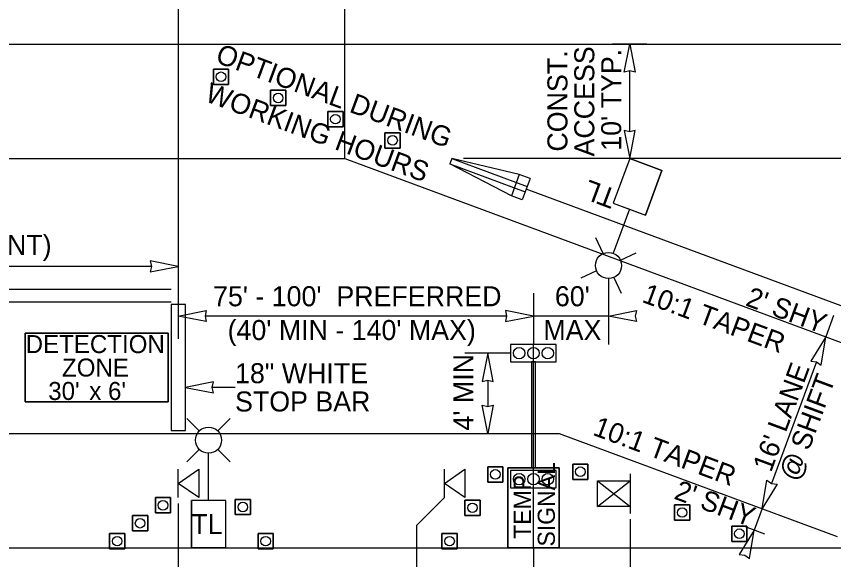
# Model space of a CAD drawing. Extents: x 99977 to 100176, y 99905 to 100011.
# Drawn here: x 100009.291 to 100012.15, y 100006.138 to 100008.036 of the extents above; entities that cross this region are included whole.
import ezdxf

# ---------------------------------------------------------------- set-up
doc = ezdxf.new("R2010")
doc.units = 0
for name, color, linetype in [('RD_ED_ShoulderPavedEdge', 7, 'Continuous'), ('RD_MK_LineEdgeWhite', 7, 'Continuous'), ('RD_MK_LineNoPass', 7, 'Continuous'), ('TR_WZ_BarrierTemp', 7, 'Continuous'), ('TR_WZ_PortableLightStandard', 7, 'Continuous'), ('TR_WZ_PortableSignMount5ftMinBlk-Wht', 7, 'Continuous'), ('TR_WZ_PortableSignMountBlk-Wht', 7, 'Continuous'), ('TR_WZ_ScaleTerminalEndSection', 7, 'Continuous'), ('TR_WZ_TempSignal', 7, 'Continuous'), ('TR_WZ_TrafficCone', 7, 'Continuous'), ('TR_WZ_WorkZoneDetails', 7, 'Continuous'), ('TR_WZ_WorkZoneTextCurrent', 7, 'Continuous')]:
    doc.layers.add(name, color=color, linetype=linetype)

msp = doc.modelspace()

# ---------------------------------------------------------------- linework, layer by layer
at = {"layer": 'RD_ED_ShoulderPavedEdge'}
for p, q in [((100000.1076, 100007.9393), (100015.45, 100007.9393)), ((100000.1076, 100006.1793), (100015.45, 100006.1793))]:
    msp.add_line(p, q, dxfattribs=at)
at = {"layer": 'RD_MK_LineEdgeWhite'}
for p, q in [((100000.1076, 100007.5393), (100010.4406, 100007.5393)), ((100010.4406, 100007.5393), (100012.9246, 100006.6193)), ((100000.1076, 100006.5793), (100011.1899, 100006.5793)), ((100011.1899, 100006.5793), (100012.1619, 100006.2193))]:
    msp.add_line(p, q, dxfattribs=at)
at = {"layer": 'RD_MK_LineNoPass'}
for p, q in [((100006.4076, 100007.0826), (100009.8326, 100007.0826)), ((100006.4076, 100007.0393), (100009.8326, 100007.0393))]:
    msp.add_line(p, q, dxfattribs=at)
at = {"layer": 'TR_WZ_BarrierTemp'}
msp.add_line((100012.9895, 100006.7232), (100011.074, 100007.4327), dxfattribs=at)
at = {"layer": 'TR_WZ_PortableLightStandard'}
for p, q in [((100011.4367, 100007.5393), (100011.3791, 100007.3837)), ((100011.4367, 100007.5393), (100011.3791, 100007.3837)), ((100011.4367, 100007.5393), (100011.5492, 100007.4976)), ((100011.5492, 100007.4976), (100011.4916, 100007.342)), ((100011.4916, 100007.342), (100011.5492, 100007.4976)), ((100011.4353, 100007.3628), (100011.3782, 100007.2087)), ((100011.3791, 100007.3837), (100011.4916, 100007.342)), ((100011.3432, 100007.2073), (100011.3178, 100007.2626)), ((100011.4039, 100007.1848), (100011.4593, 100007.2103)), ((100011.3207, 100007.1467), (100011.2655, 100007.1212)), ((100011.3815, 100007.1242), (100011.4069, 100007.0688)), ((100009.9312, 100006.5878), (100009.8881, 100006.6309)), ((100009.996, 100006.5878), (100010.0389, 100006.6309)), ((100009.9312, 100006.5231), (100009.8881, 100006.48)), ((100009.9636, 100006.3453), (100009.9636, 100006.5097)), ((100009.996, 100006.5231), (100010.0389, 100006.48)), ((100009.9036, 100006.1793), (100009.9036, 100006.3453)), ((100010.0236, 100006.3453), (100009.9036, 100006.3453)), ((100009.9036, 100006.3453), (100009.9036, 100006.1793)), ((100010.0236, 100006.1793), (100010.0236, 100006.3453)), ((100010.0236, 100006.1793), (100010.0236, 100006.3453)), ((100010.0236, 100006.1793), (100009.9036, 100006.1793))]:
    msp.add_line(p, q, dxfattribs=at)
for points in [[(100011.5492, 100007.4976), (100011.493, 100007.5185), (100011.4367, 100007.5393)], [(100011.3791, 100007.3837), (100011.4353, 100007.3628), (100011.4916, 100007.342)], [(100010.0236, 100006.3453), (100009.9636, 100006.3453), (100009.9036, 100006.3453)], [(100009.9036, 100006.1793), (100009.9636, 100006.1793), (100010.0236, 100006.1793)]]:
    msp.add_lwpolyline(points, dxfattribs=at)
for centre in [(100011.3623, 100007.1657), (100011.3623, 100007.1657), (100009.9635, 100006.5555), (100009.9635, 100006.5555)]:
    msp.add_circle(centre, 0.0457, dxfattribs=at)
at = {"layer": 'TR_WZ_PortableSignMount5ftMinBlk-Wht'}
for p, q in [((100011.4384, 100006.4376), (100011.4384, 100006.2997)), ((100011.3233, 100006.3238), (100011.4384, 100006.4134)), ((100011.3233, 100006.4134), (100011.4384, 100006.3238)), ((100011.3807, 100006.3685), (100011.3807, 100006.3685)), ((100011.3808, 100006.3686), (100011.3808, 100006.3686))]:
    msp.add_line(p, q, dxfattribs=at)
msp.add_lwpolyline([(100011.3233, 100006.3238), (100011.3233, 100006.4134), (100011.4384, 100006.4134), (100011.4384, 100006.3238)], close=True, dxfattribs=at)
at = {"layer": 'TR_WZ_PortableSignMountBlk-Wht'}
for p, q in [((100009.8576, 100006.3547), (100009.8576, 100006.4547)), ((100010.7884, 100006.3547), (100010.7884, 100006.4547))]:
    msp.add_line(p, q, dxfattribs=at)
for points in [[(100009.8576, 100006.4046), (100009.9294, 100006.4547), (100009.9294, 100006.3547)], [(100010.7884, 100006.4046), (100010.8602, 100006.4547), (100010.8602, 100006.3547)]]:
    msp.add_lwpolyline(points, close=True, dxfattribs=at)
at = {"layer": 'TR_WZ_ScaleTerminalEndSection'}
for p, q in [((100010.8149, 100007.5393), (100010.8079, 100007.5206)), ((100010.8149, 100007.5393), (100011.0775, 100007.4421)), ((100011.0504, 100007.4841), (100010.8149, 100007.5393)), ((100010.8079, 100007.5206), (100011.0705, 100007.4233)), ((100011.0226, 100007.4091), (100010.8079, 100007.5206)), ((100011.0504, 100007.4841), (100011.0226, 100007.4091)), ((100011.0879, 100007.4702), (100011.0504, 100007.4841)), ((100011.0879, 100007.4702), (100011.0601, 100007.3952)), ((100011.0601, 100007.3952), (100011.0226, 100007.4091))]:
    msp.add_line(p, q, dxfattribs=at)
at = {"layer": 'TR_WZ_TempSignal'}
for p, q in [((100011.02, 100006.8893), (100011.02, 100006.8293)), ((100011.1798, 100006.8893), (100011.02, 100006.8893)), ((100011.0999, 100006.1789), (100011.0999, 100006.8893)), ((100011.1798, 100006.8293), (100011.1798, 100006.8893)), ((100011.02, 100006.8293), (100011.1798, 100006.8293)), ((100011.0932, 100006.8293), (100011.0932, 100006.4591)), ((100011.1065, 100006.8293), (100011.0932, 100006.8293)), ((100011.1065, 100006.4591), (100011.1065, 100006.8293)), ((100011.0098, 100006.1789), (100011.0098, 100006.4591)), ((100011.0098, 100006.4591), (100011.1899, 100006.4591)), ((100011.0932, 100006.4591), (100011.0098, 100006.4591)), ((100011.0098, 100006.4591), (100011.0098, 100006.1789)), ((100011.02, 100006.4491), (100011.02, 100006.3891)), ((100011.1798, 100006.4491), (100011.02, 100006.4491)), ((100011.0932, 100006.4591), (100011.1065, 100006.4591)), ((100011.1065, 100006.4591), (100011.0932, 100006.4591)), ((100011.1899, 100006.4591), (100011.1065, 100006.4591)), ((100011.1798, 100006.3891), (100011.1798, 100006.4491)), ((100011.1899, 100006.4591), (100011.1899, 100006.1789)), ((100011.1899, 100006.1789), (100011.1899, 100006.4591)), ((100011.02, 100006.3891), (100011.1798, 100006.3891)), ((100011.1899, 100006.1789), (100011.0098, 100006.1789)), ((100011.0098, 100006.1789), (100011.1899, 100006.1789))]:
    msp.add_line(p, q, dxfattribs=at)
for points in [[(100011.1798, 100006.8293), (100011.1798, 100006.8893), (100011.02, 100006.8893), (100011.02, 100006.8293), (100011.1798, 100006.8293)], [(100011.1798, 100006.3891), (100011.1798, 100006.4491), (100011.02, 100006.4491), (100011.02, 100006.3891), (100011.1798, 100006.3891)]]:
    msp.add_lwpolyline(points, dxfattribs=at)
for centre in [(100011.0499, 100006.8593), (100011.0499, 100006.8593), (100011.0999, 100006.8593), (100011.0999, 100006.8593), (100011.1498, 100006.8593), (100011.1498, 100006.8593), (100011.0499, 100006.4191), (100011.0499, 100006.4191), (100011.0999, 100006.4191), (100011.0999, 100006.4191), (100011.1498, 100006.4191), (100011.1498, 100006.4191)]:
    msp.add_circle(centre, 0.02, dxfattribs=at)
at = {"layer": 'TR_WZ_TrafficCone'}
for points in [[(100010.0339, 100007.8518), (100009.9805, 100007.8518), (100009.9805, 100007.7984), (100010.0339, 100007.7984), (100010.0339, 100007.8518)], [(100010.0339, 100007.7984), (100009.9805, 100007.7984), (100009.9805, 100007.8518), (100010.0339, 100007.8518), (100010.0339, 100007.7984)], [(100010.2339, 100007.7777), (100010.1805, 100007.7777), (100010.1805, 100007.7244), (100010.2339, 100007.7244), (100010.2339, 100007.7777)], [(100010.2339, 100007.7244), (100010.1805, 100007.7244), (100010.1805, 100007.7777), (100010.2339, 100007.7777), (100010.2339, 100007.7244)], [(100010.4339, 100007.7036), (100010.3805, 100007.7036), (100010.3805, 100007.6503), (100010.4339, 100007.6503), (100010.4339, 100007.7036)], [(100010.4339, 100007.6503), (100010.3805, 100007.6503), (100010.3805, 100007.7036), (100010.4339, 100007.7036), (100010.4339, 100007.6503)], [(100010.6339, 100007.6295), (100010.5805, 100007.6295), (100010.5805, 100007.5762), (100010.6339, 100007.5762), (100010.6339, 100007.6295)], [(100010.6339, 100007.5762), (100010.5805, 100007.5762), (100010.5805, 100007.6295), (100010.6339, 100007.6295), (100010.6339, 100007.5762)], [(100010.9931, 100006.4626), (100010.9398, 100006.4626), (100010.9398, 100006.4093), (100010.9931, 100006.4093), (100010.9931, 100006.4626)], [(100010.9931, 100006.4093), (100010.9398, 100006.4093), (100010.9398, 100006.4626), (100010.9931, 100006.4626), (100010.9931, 100006.4093)], [(100011.237, 100006.472), (100011.2903, 100006.472), (100011.2903, 100006.4187), (100011.237, 100006.4187), (100011.237, 100006.472)], [(100011.237, 100006.4187), (100011.2903, 100006.4187), (100011.2903, 100006.472), (100011.237, 100006.472), (100011.237, 100006.4187)], [(100009.7775, 100006.3547), (100009.8309, 100006.3547), (100009.8309, 100006.3013), (100009.7775, 100006.3013), (100009.7775, 100006.3547)], [(100009.7775, 100006.3013), (100009.8309, 100006.3013), (100009.8309, 100006.3547), (100009.7775, 100006.3547), (100009.7775, 100006.3013)], [(100010.1101, 100006.3486), (100010.0568, 100006.3486), (100010.0568, 100006.2953), (100010.1101, 100006.2953), (100010.1101, 100006.3486)], [(100010.1101, 100006.2953), (100010.0568, 100006.2953), (100010.0568, 100006.3486), (100010.1101, 100006.3486), (100010.1101, 100006.2953)], [(100010.8599, 100006.346), (100010.9132, 100006.346), (100010.9132, 100006.2926), (100010.8599, 100006.2926), (100010.8599, 100006.346)], [(100010.8599, 100006.2926), (100010.9132, 100006.2926), (100010.9132, 100006.346), (100010.8599, 100006.346), (100010.8599, 100006.2926)], [(100011.5933, 100006.3294), (100011.6466, 100006.3294), (100011.6466, 100006.2761), (100011.5933, 100006.2761), (100011.5933, 100006.3294)], [(100011.5933, 100006.2761), (100011.6466, 100006.2761), (100011.6466, 100006.3294), (100011.5933, 100006.3294), (100011.5933, 100006.2761)], [(100009.6975, 100006.292), (100009.7509, 100006.292), (100009.7509, 100006.2387), (100009.6975, 100006.2387), (100009.6975, 100006.292)], [(100009.6975, 100006.2387), (100009.7509, 100006.2387), (100009.7509, 100006.292), (100009.6975, 100006.292), (100009.6975, 100006.2387)], [(100011.7933, 100006.2553), (100011.8466, 100006.2553), (100011.8466, 100006.202), (100011.7933, 100006.202), (100011.7933, 100006.2553)], [(100011.7933, 100006.202), (100011.8466, 100006.202), (100011.8466, 100006.2553), (100011.7933, 100006.2553), (100011.7933, 100006.202)], [(100009.6175, 100006.2293), (100009.6709, 100006.2293), (100009.6709, 100006.176), (100009.6175, 100006.176), (100009.6175, 100006.2293)], [(100009.6175, 100006.176), (100009.6709, 100006.176), (100009.6709, 100006.2293), (100009.6175, 100006.2293), (100009.6175, 100006.176)], [(100010.1901, 100006.2293), (100010.1368, 100006.2293), (100010.1368, 100006.176), (100010.1901, 100006.176), (100010.1901, 100006.2293)], [(100010.1901, 100006.176), (100010.1368, 100006.176), (100010.1368, 100006.2293), (100010.1901, 100006.2293), (100010.1901, 100006.176)], [(100010.7799, 100006.2293), (100010.8332, 100006.2293), (100010.8332, 100006.176), (100010.7799, 100006.176), (100010.7799, 100006.2293)], [(100010.7799, 100006.176), (100010.8332, 100006.176), (100010.8332, 100006.2293), (100010.7799, 100006.2293), (100010.7799, 100006.176)]]:
    msp.add_lwpolyline(points, dxfattribs=at)
for centre in [(100010.0072, 100007.8251), (100010.2072, 100007.751), (100010.4072, 100007.677), (100010.6072, 100007.6029), (100010.9665, 100006.436), (100011.2637, 100006.4453), (100009.8042, 100006.328), (100010.0835, 100006.3219), (100010.8865, 100006.3193), (100011.62, 100006.3027), (100009.7242, 100006.2653), (100011.82, 100006.2287), (100009.6442, 100006.2026), (100010.1635, 100006.2026), (100010.8065, 100006.2026)]:
    msp.add_circle(centre, 0.0167, dxfattribs=at)
at = {"layer": 'TR_WZ_WorkZoneDetails'}
for p, q in [((100009.8576, 100008.2793), (100009.8576, 100006.9093)), ((100010.4406, 100007.5393), (100010.4406, 100008.2793)), ((100011.4967, 100007.9393), (100011.3767, 100007.9393)), ((100011.4367, 100007.633), (100011.4367, 100007.8456)), ((100012.7386, 100007.5393), (100010.8549, 100007.5393)), ((100009.7638, 100007.1626), (100006.5013, 100007.1626)), ((100011.3623, 100007.12), (100011.3623, 100006.8893)), ((100011.0999, 100007.0693), (100011.0999, 100006.8893)), ((100011.0061, 100006.9893), (100009.9513, 100006.9893)), ((100011.3623, 100006.9893), (100011.0999, 100006.9893)), ((100012.1497, 100006.9916), (100012.1219, 100006.9166)), ((100011.02, 100006.8593), (100010.86, 100006.8593)), ((100012.0894, 100006.8287), (100011.9322, 100006.4043)), ((100010.94, 100006.7656), (100010.94, 100006.673)), ((100010.0563, 100006.7401), (100009.9763, 100006.7401)), ((100009.8576, 100006.3347), (100009.8576, 100005.8393)), ((100010.7884, 100006.3547), (100010.6914, 100006.2577)), ((100011.8996, 100006.3164), (100011.8718, 100006.2414)), ((100011.4384, 100006.2797), (100011.4384, 100005.8393)), ((100010.6914, 100006.2577), (100010.6914, 100005.8393)), ((100011.9094, 100006.2275), (100011.8322, 100006.2561)), ((100011.0999, 100006.1793), (100011.0999, 100004.4092))]:
    msp.add_line(p, q, dxfattribs=at)
for points in [[(100011.4367, 100007.9393), (100011.456, 100007.841), (100011.4367, 100007.8456), (100011.4174, 100007.841)], [(100011.4367, 100007.5393), (100011.456, 100007.6376), (100011.4367, 100007.633), (100011.4174, 100007.6376)], [(100009.8576, 100007.1626), (100009.7593, 100007.1819), (100009.7638, 100007.1626), (100009.7593, 100007.1434)], [(100009.8576, 100006.9893), (100009.9558, 100007.0085), (100009.9513, 100006.9893), (100009.9558, 100006.97)], [(100011.0999, 100006.9893), (100011.0016, 100007.0085), (100011.0061, 100006.9893), (100011.0016, 100006.97)], [(100011.3623, 100006.9893), (100011.4606, 100007.0085), (100011.4561, 100006.9893), (100011.4606, 100006.97)], [(100012.1219, 100006.9166), (100012.0697, 100006.8311), (100012.0894, 100006.8287), (100012.1058, 100006.8177)], [(100010.94, 100006.8593), (100010.9207, 100006.761), (100010.94, 100006.7656), (100010.9593, 100006.761)], [(100009.8826, 100006.7393), (100009.981, 100006.7209), (100009.9763, 100006.7401), (100009.9807, 100006.7594)], [(100010.94, 100006.5793), (100010.9207, 100006.6776), (100010.94, 100006.673), (100010.9593, 100006.6776)], [(100011.8996, 100006.3164), (100011.9157, 100006.4153), (100011.9322, 100006.4043), (100011.9518, 100006.4019)], [(100011.8718, 100006.2414), (100011.8196, 100006.156), (100011.8393, 100006.1535), (100011.8558, 100006.1426)]]:
    msp.add_lwpolyline(points, close=True, dxfattribs=at)
for points in [[(100009.8326, 100006.5893), (100009.8826, 100006.5893), (100009.8826, 100007.0293), (100009.8326, 100007.0293), (100009.8326, 100006.5893)], [(100009.8326, 100006.5893), (100009.8826, 100006.5893), (100009.8826, 100007.0293), (100009.8326, 100007.0293), (100009.8326, 100006.5893)], [(100009.3226, 100006.9293), (100009.8226, 100006.9293), (100009.8226, 100006.6893), (100009.3226, 100006.6893), (100009.3226, 100006.9293)], [(100009.3226, 100006.6893), (100009.8226, 100006.6893), (100009.8226, 100006.9293), (100009.3226, 100006.9293), (100009.3226, 100006.6893)]]:
    msp.add_lwpolyline(points, dxfattribs=at)

# ---------------------------------------------------------------- texts
at = {"layer": 'TR_WZ_PortableLightStandard'}
msp.add_text('TL', height=0.07, rotation=159.6769, dxfattribs=at).set_placement((100011.3958, 100007.4287))
msp.add_text('TL', height=0.07, dxfattribs=at).set_placement((100009.9034, 100006.2273))
at = {"layer": 'TR_WZ_TempSignal'}
for s, p in [('SIGNAL', (100011.1748, 100006.184)), ('TEMP', (100011.0908, 100006.2111))]:
    msp.add_text(s, height=0.06, rotation=90, dxfattribs=at).set_placement(p)
at = {"layer": 'TR_WZ_WorkZoneDetails'}
for s, p in [('DETECTION', (100009.3239, 100006.8597)), ('ZONE', (100009.4511, 100006.7778)), ("30'", (100009.4029, 100006.6959)), ("x 6'", (100009.5465, 100006.6959))]:
    msp.add_text(s, height=0.063, dxfattribs=at).set_placement(p)
at = {"layer": 'TR_WZ_WorkZoneTextCurrent'}
for s, rotation, p in [('OPTIONAL DURING', 339.6769, (100009.984, 100007.8768)), ('CONST.', 90, (100011.2187, 100007.5637)), ('ACCESS', 90, (100011.3127, 100007.5465)), ("10' TYP.", 90, (100011.4067, 100007.5666)), ('WORKING HOURS', 339.6769, (100009.9472, 100007.7411)), ("75' - 100'  PREFERRED", 360, (100009.9795, 100007.0233)), ("60'", 360, (100011.1748, 100007.0233)), ('10:1 TAPER', 339.6769, (100011.4758, 100007.0392)), ("2' SHY", 339.6769, (100011.838, 100007.0271)), ("(40' MIN - 140' MAX)", 360, (100010.0303, 100006.9053)), ('MAX', 360, (100011.1346, 100006.9053)), ("4' MIN", 90, (100010.89, 100006.5891)), ("16' LANE", 69.6769, (100011.9308, 100006.4408)), ('SHIFT', 69.6769, (100012.063, 100006.5156)), ('10:1 TAPER', 339.6769, (100011.3038, 100006.5747)), ('@', 69.6769, (100012.023, 100006.4077)), ("2' SHY", 339.6769, (100011.5879, 100006.3519))]:
    msp.add_text(s, height=0.07, rotation=rotation, dxfattribs=at).set_placement(p)
for s, p in [('(SEE NOTE 11, WITHIN EXISTING PASSING ZONES IF PRESENT)', (100006.5333, 100007.2026)), ('18" WHITE', (100010.0563, 100006.7545)), ('STOP BAR', (100010.0563, 100006.6557))]:
    msp.add_text(s, height=0.07, dxfattribs=at).set_placement(p)

doc.saveas('drawing.dxf')
